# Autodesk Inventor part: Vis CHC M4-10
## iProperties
Shininess: 64.0
Length Units: 11269
Angle Units: 11279
Time Units: 11290
Mass Units: 11283
Length Display Precision: 3
Angle Display Precision: 2
Compacted: True
Part Number: Vis CHC M4-10
Document SubType Name: Modeling
Created: 2006-01
Material: Par défaut
Designer: Fricot
Density: 0.0
Volumn: 0.0
Area: 0.0
PropertySet Name: Model Information
Control State: 0
Master: False
Checked Out: False
Author: Fricot
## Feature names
1. Base1
